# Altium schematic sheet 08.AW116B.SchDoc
size A4; CheckedBy: 赵金生; Author: 黄雄波; CompanyName: 广州周立功的单片机科技有限公司; DocumentNumber: 7; SheetNumber: 7; SheetTotal: 8; PageSetup: Record=PageOptions¦CenterHorizontal=True¦CenterVertical=True¦PrintScale=1.00¦XCorrection=1.00¦YCorrection=1.00¦PrintKind=0¦BorderSize=5000000¦LeftOffset=0¦BottomOffset=0¦Orientation=2¦PaperLength=1000¦PaperWidth=1000¦Scale=100¦PaperSource=7¦PrintQuality=600¦MediaType=1¦DitherType=10¦PaperKind=A4¦PrintScaleMode=1; DesignDate: 2018-6-14; CheckDate: 2018-6-14; SheetName: AW116B; SheetVersion: V1.01; ProductName: 开发套件; ProductModel: AM116BLE
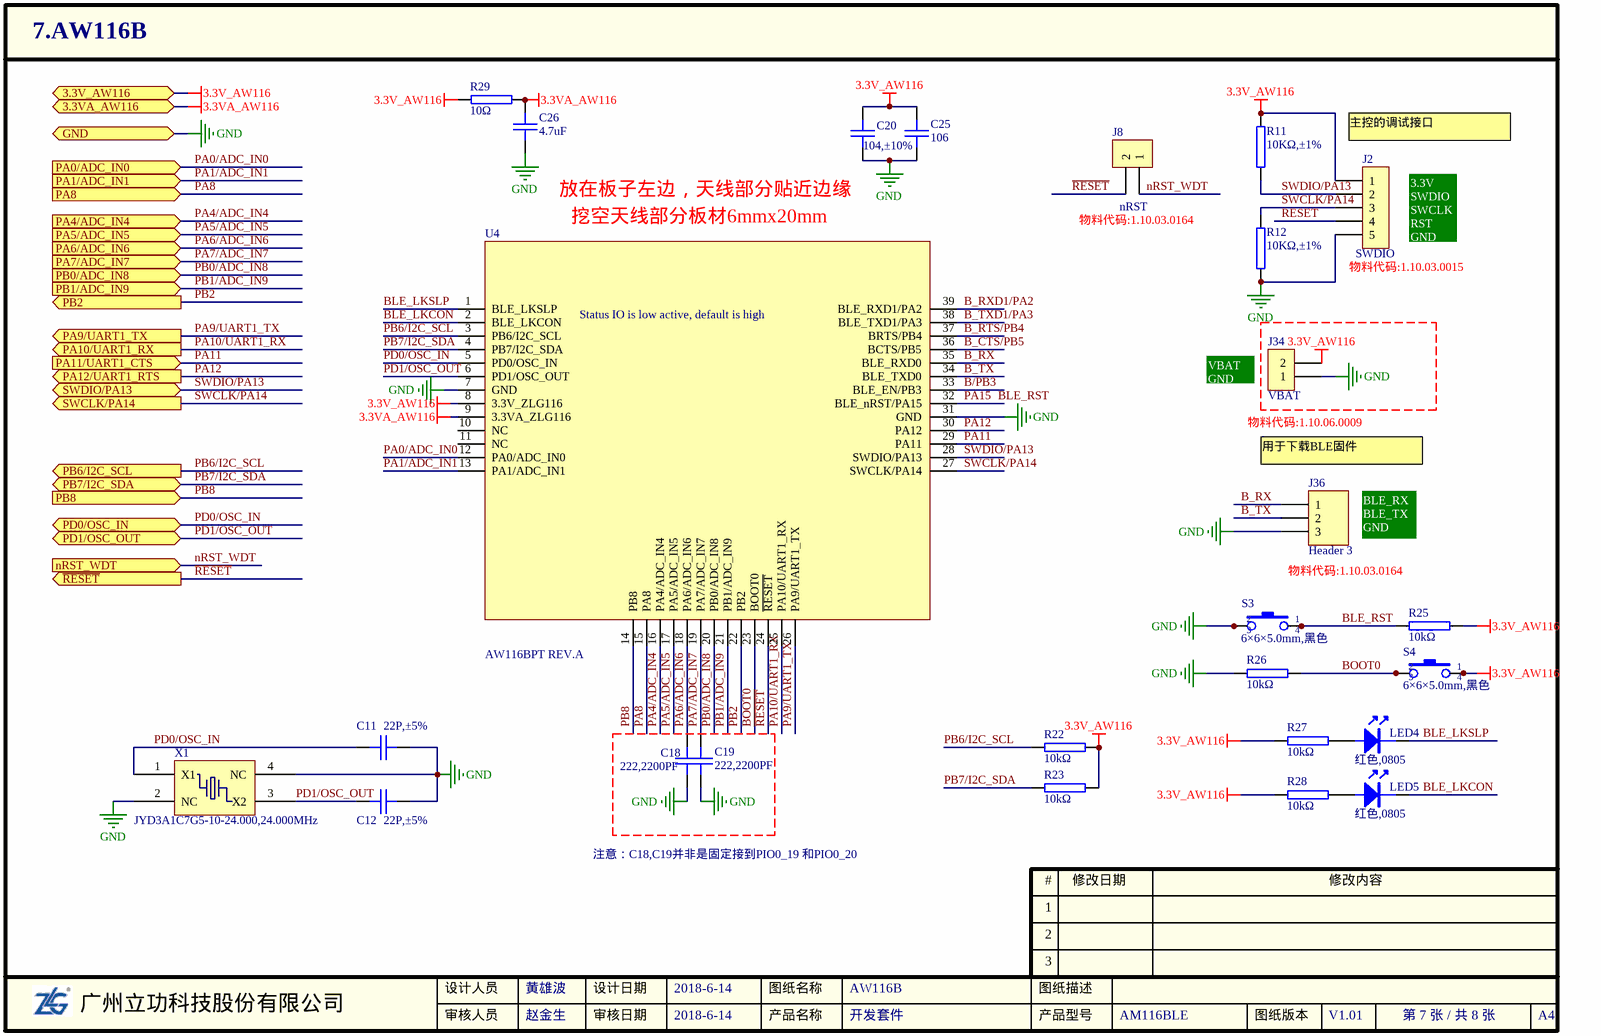
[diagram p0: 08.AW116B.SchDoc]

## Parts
C11  22P,±5%  [0603C]
C12  22P,±5%  [0603C]
C18  222,2200PF  [0603C]
C19  222,2200PF  [0603C]
C20  104,±10%  [0603C]
C25  106  [0805C]
C26  4.7uF  [0603C]
J2  SWDIO  [SIP-5-2.54-6.0-R90]
J8  nRST  [SIP-2-2.54]
J34  VBAT  [CN-2-2.54]
J36  Header 3  [SIP-3]
LED4  value 红色,0805  [LED-0805]  (hidden comment: LED1)
LED5  value 红色,0805  [LED-0805]  (hidden comment: LED1)
R11  10KΩ,±1%  [0603R]
R12  10KΩ,±1%  [0603R]
R22  10kΩ  [0603R]
R23  10kΩ  [0603R]
R25  10kΩ  [0603R]
R26  10kΩ  [0603R]
R27  10kΩ  [0603R]
R28  10kΩ  [0603R]
R29  10Ω  [0603R]
S3  value 6×6×5.0mm,黑色  [KEY-6S]  (hidden comment: SW-PB4P)
S4  value 6×6×5.0mm,黑色  [KEY-6S]  (hidden comment: SW-PB4P)
U4  AW116BPT REV.A  [AW824BPT]
X1  JYD3A1C7G5-10-24.000,24.000MHz  [XTAL4-3.2X2.5]

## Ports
3.3V_AW116, 3.3VA_AW116, GND, nRST_WDT (in), PA0/ADC_IN0 (in), PA1/ADC_IN1 (in), PA4/ADC_IN4 (in), PA5/ADC_IN5 (in), PA6/ADC_IN6 (in), PA7/ADC_IN7 (in), PA8 (in), PA9/UART1_TX (out), PA10/UART1_RX (out), PA11/UART1_CTS (in), PA12/UART1_RTS (out), PB0/ADC_IN8 (in), PB1/ADC_IN9 (in), PB2 (out), PB6/I2C_SCL (out), PB7/I2C_SDA (bidir), PB8 (in), PD0/OSC_IN (bidir), PD1/OSC_OUT (bidir), SWCLK/PA14 (out), SWDIO/PA13 (bidir), ~{RESET} (out)

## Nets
3.3V_AW116: C20.1 C25.1 J2.1 J34.2 R11.2 R22.2 R23.2 R25.2 R27.1 R28.1 R29.2 S4.1 S4.4 U4.8(3.3V_ZLG116) ; port 3.3V_AW116
3.3VA_AW116: C26.1 R29.1 U4.9(3.3VA_ZLG116) ; port 3.3VA_AW116
GND: C11.2 C12.2 C18.2 C19.2 C20.2 C25.2 C26.2 J2.5 J34.1 J36.3 R12.1 R26.1 S3.2 S3.3 U4.7(GND) U4.31(GND) X1.2(NC) X1.4(NC) ; port GND
B/PB3: U4.33(BLE_EN/PB3)
B_CTS/PB5: U4.36(BCTS/PB5)
B_RTS/PB4: U4.37(BRTS/PB4)
B_RX: J36.1 U4.35(BLE_RXD0)
B_RXD1/PA2: U4.39(BLE_RXD1/PA2)
B_TX: J36.2 U4.34(BLE_TXD0)
B_TXD1/PA3: U4.38(BLE_TXD1/PA3)
BLE_LKCON: LED5.2 U4.2(BLE_LKCON)
BLE_LKSLP: LED4.2 U4.1(BLE_LKSLP)
BLE_RST: R25.1 S3.1 S3.4 U4.32(BLE_nRST/PA15)  [also labelled PA15]
BOOT0: R26.2 S4.2 S4.3 U4.23(BOOT0)
nRST_WDT: J8.1 ; port nRST_WDT
PA0/ADC_IN0: U4.12(PA0/ADC_IN0) ; port PA0/ADC_IN0
PA1/ADC_IN1: U4.13(PA1/ADC_IN1) ; port PA1/ADC_IN1
PA4/ADC_IN4: U4.16(PA4/ADC_IN4) ; port PA4/ADC_IN4
PA5/ADC_IN5: U4.17(PA5/ADC_IN5) ; port PA5/ADC_IN5
PA6/ADC_IN6: C18.1 U4.18(PA6/ADC_IN6) ; port PA6/ADC_IN6
PA7/ADC_IN7: C19.1 U4.19(PA7/ADC_IN7) ; port PA7/ADC_IN7
PA8: U4.15(PA8) ; port PA8
PA9/UART1_TX: U4.26(PA9/UART1_TX) ; port PA9/UART1_TX
PA10/UART1_RX: U4.25(PA10/UART1_RX) ; port PA10/UART1_RX
PA11: U4.29(PA11) ; port PA11/UART1_CTS
PA12: U4.30(PA12) ; port PA12/UART1_RTS
PB0/ADC_IN8: U4.20(PB0/ADC_IN8) ; port PB0/ADC_IN8
PB1/ADC_IN9: U4.21(PB1/ADC_IN9) ; port PB1/ADC_IN9
PB2: U4.22(PB2) ; port PB2
PB6/I2C_SCL: R22.1 U4.3(PB6/I2C_SCL) ; port PB6/I2C_SCL
PB7/I2C_SDA: R23.1 U4.4(PB7/I2C_SDA) ; port PB7/I2C_SDA
PB8: U4.14(PB8) ; port PB8
PD0/OSC_IN: C11.1 U4.5(PD0/OSC_IN) X1.1(X1) ; port PD0/OSC_IN
PD1/OSC_OUT: C12.1 U4.6(PD1/OSC_OUT) X1.3(X2) ; port PD1/OSC_OUT
~{RESET}: J2.4 J8.2 U4.24(~{RESET}) ; port ~{RESET}
SWCLK/PA14: J2.3 R12.2 U4.27(SWCLK/PA14) ; port SWCLK/PA14
SWDIO/PA13: J2.2 R11.1 U4.28(SWDIO/PA13) ; port SWDIO/PA13
NetLED4_1: LED4.1 R27.2
NetLED5_1: LED5.1 R28.2

Not connected (* = marked no-connect by the designer): U4 10(NC) 11(NC)

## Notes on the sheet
- (near J2) 主控的调试接口
- (near C26) 放在板子左边，天线部分贴近边缘
- 挖空天线部分板材6mmx20mm
- (near J8) 物料代码:1.10.03.0164
- (near J2) 3.3V
  SWDIO
  SWCLK
  RST
  GND
- (near J2) 物料代码:1.10.03.0015
- (near J34) VBAT
  GND
- (near J34) 物料代码:1.10.06.0009
- 用于下载BLE固件
- 物料代码:1.10.03.0164
- BLE_RX
  BLE_TX
  GND
- 注意：C18,C19并非是固定接到PIO0_19 和PIO0_20

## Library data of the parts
C11 C12 = 1.02.01.0005: 22P,±5%,50V,COG,0603,*,RoHS; 名称: 电容; 封装: 0603; 设备封装名称: C0603_22P_COG_50V_5%; 厂商: muRata; 贴片和直插: SMT; 器件优选方案: 临时/偏门物料/不主推物料，谨慎选用
C18 C19 = 1.02.01.0048: GRM188R71H222KA01D,222,2200PF,±10%,50V,X7R,0603,RoHS; 名称: 电容; 封装: 0603; 设备封装名称: C0603_222_X7R_50V_10%; 厂商: muRata; 贴片和直插: SMT; 器件优选方案: 正常状态，可以选用
C20 = 1.02.01.0032: 104,±10%,50V,X7R,0603,*,RoHS; 名称: 电容; 封装: 0603; 设备封装名称: C0603_104_X7R_50V_10%; 厂商: muRata; 贴片和直插: SMT; 器件优选方案: 量产物料,优先选用
C25 = 1.02.02.0055: 106,10μF,±10%,10V,X5R,0805,RoHS; 名称: 电容; 封装: 0805; 贴片和直插: SMT; 器件优选方案: 量产物料,优先选用; 设备封装名称: C0805_106_X5R_10V_10%
C26 = 1.02.01.0080: GRM188R61A475KE15D,4.7uF,±10%,10V,X5R,0603,muRata,RoHS; 名称: 电容; 封装: 0603; 贴片和直插: SMT; PCB备注: 160602yjh; 器件优选方案: 正常状态，可以选用
J2 = CON5: Connector; 物料代码: 1.10.03.0015
J8 = CON2: Connector; 物料代码: 1.10.03.0164
J34 = 1.10.06.0009: 2.54-2T,180°,,*; 名称: 插座; 贴片和直插: THT; PCB备注: xhm-lq-wyy-150123
J36 = Header 3: Header, 3-Pin; 物料代码: 1.10.03.0164
LED4 LED5 = 1.04.05.0001: 红色,0805,0805,RoHS; 名称: 发光二极管; 封装: 0805; 设备封装名称: LED0805-RED; 贴片和直插: SMT; 器件优选方案: 样品物料,谨慎选用
R11 R12 R22 R23 R25-R28 = 1.01.01.0052: 10KΩ,±1%,0603,*,RoHS; 名称: 电阻; 封装: 0603; 设备封装名称: R0603_10K_1%; 厂商: Ralec; 贴片和直插: SMT
R29 = 1.01.01.0007: 10Ω,0603,*,RoHS; 名称: 电阻; 封装: 0603; 设备封装名称: R0603_10R; 厂商: Ralec; 贴片和直插: SMT; 器件优选方案: 正常状态，可以选用
S3 S4 = 1.09.01.0003: 6×6×5.0mm,黑色,SMD,,*; 名称: 轻触按键; 贴片和直插: SMT
X1 = 1.07.01.0049: JYD3A1C7G5-10-24.000,24.000MHz,10pF,±30ppm,-40~85℃,SMD3225,JYEG,RoHS; 名称: 晶体; 型号: JYD3A1C7G5-10-24.000,24.000MHz,10pF±30ppm,-40~85℃; 贴片和直插: SMT; 器件优选方案: 正常状态，可以选用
